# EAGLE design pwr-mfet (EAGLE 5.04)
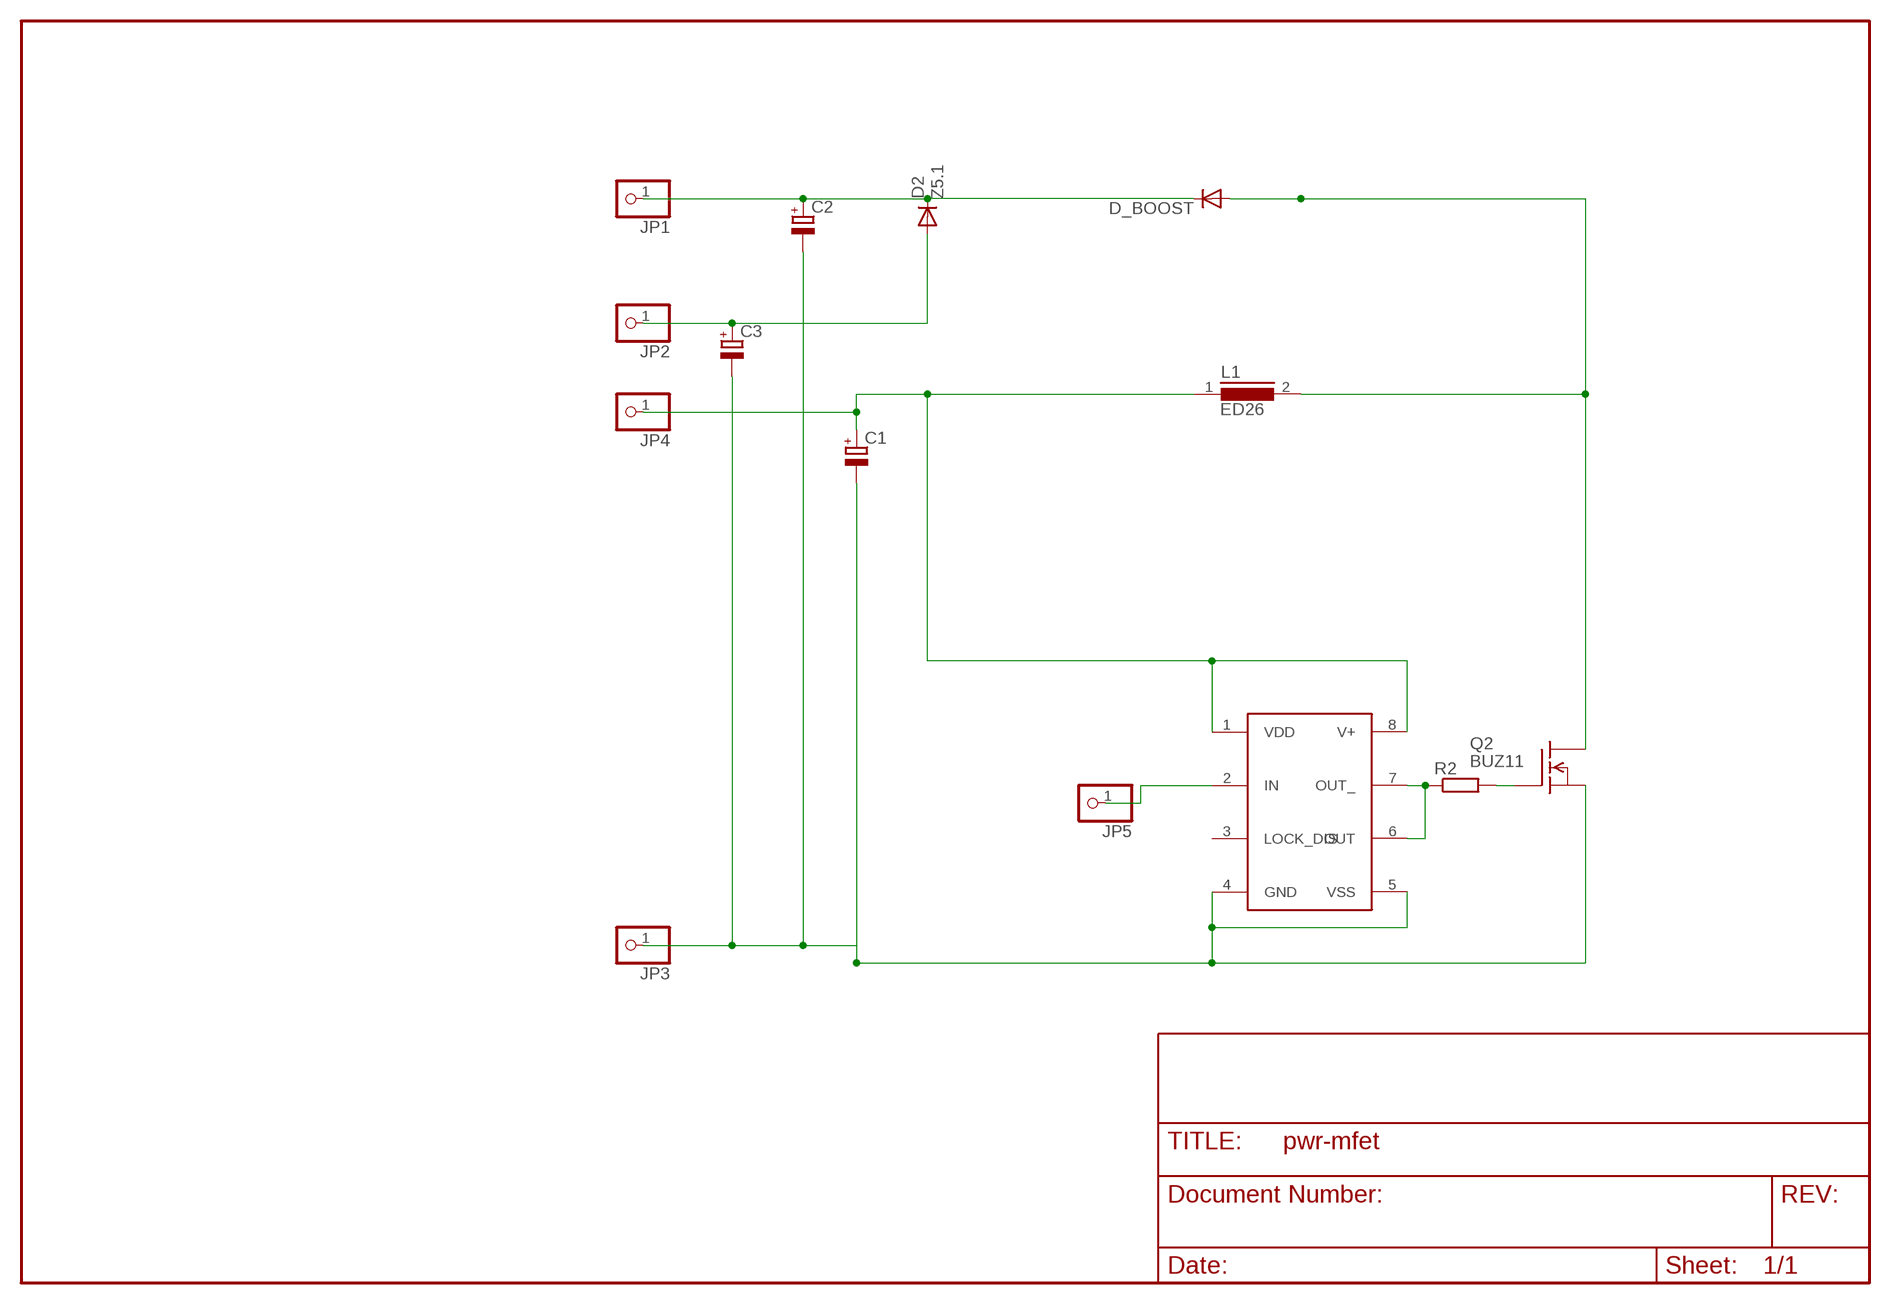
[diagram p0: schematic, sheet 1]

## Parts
C1  CPOL-EUE2.5-7  [E2,5-7]
C2  CPOL-EUE2.5-7  [E2,5-7]
C3  CPOL-EUE2-4  [E2-4]
D2  Z5.1  DIODE-D-2.5  [D-2.5]
D_BOOST  DIODE-D-10  [D-10]
IC1  TC4432X  [SO-08]
JP1  PINHD-1X1  [1X01]
JP2  PINHD-1X1  [1X01]
JP3  PINHD-1X1  [1X01]
JP4  PINHD-1X1  [1X01]
JP5  PINHD-1X1  [1X01]
L1  ED26  [ED26]
Q2  BUZ11  [TO220]
R2  R-EU_R1206  [R1206]

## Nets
GND: C1.- C2.- C3.- IC1.4(GND) IC1.5(VSS) JP3.1 Q2.3(S)
HOTSPOT: D_BOOST.A L1.2 Q2.2(D)
LOAD: C2.+ D2.C D_BOOST.C JP1.1
N$1: IC1.2(IN) JP5.1
N$2: C1.+ IC1.1(VDD) IC1.8(V+) JP4.1 L1.1
N$3: IC1.6(OUT) IC1.7(OUT_) R2.1
N$4: C3.+ D2.A JP2.1
N$6: Q2.1(G) R2.2
Unconnected: IC1.3(LOCK_DIS)

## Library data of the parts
C1-C3 = rcl(2):CPOL-EU: POLARIZED CAPACITOR, European symbol
D2 D_BOOST = diode:DIODE-: DIODE
IC1 = microchip:TC4432
JP1-JP5 = pinhead:PINHD-1X1: PIN HEADER
L1 = inductors:ED26: INDUCTOR
Q2 = transistor-fet:BUZ11: N-Channel Enhancement MOSFET 50V; 30A; 0,040Ohm
R2 = rcl-2:R-EU_: RESISTOR, European symbol

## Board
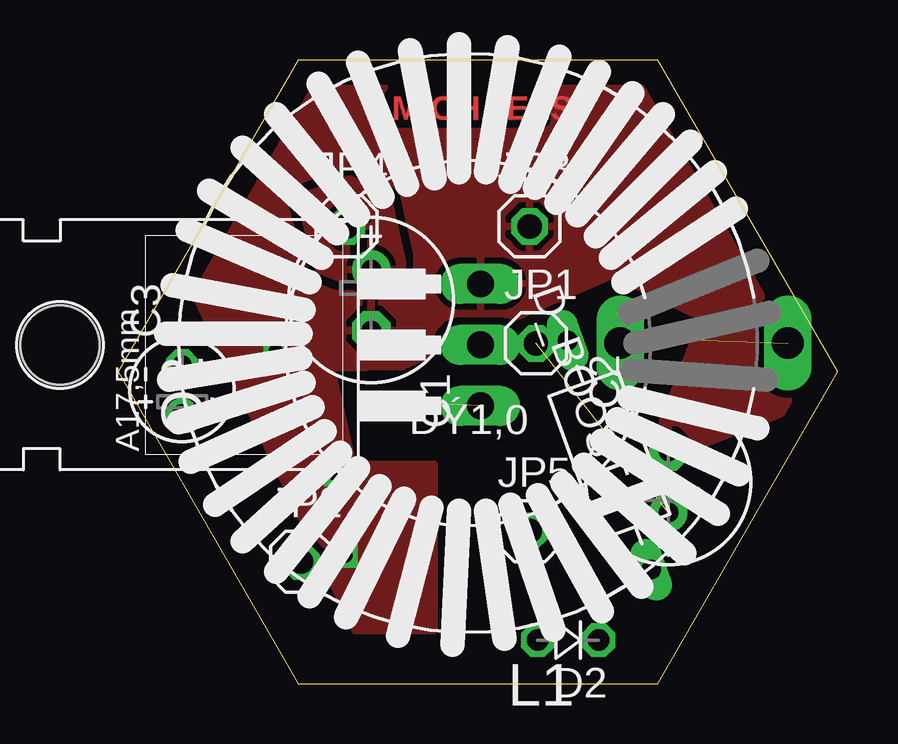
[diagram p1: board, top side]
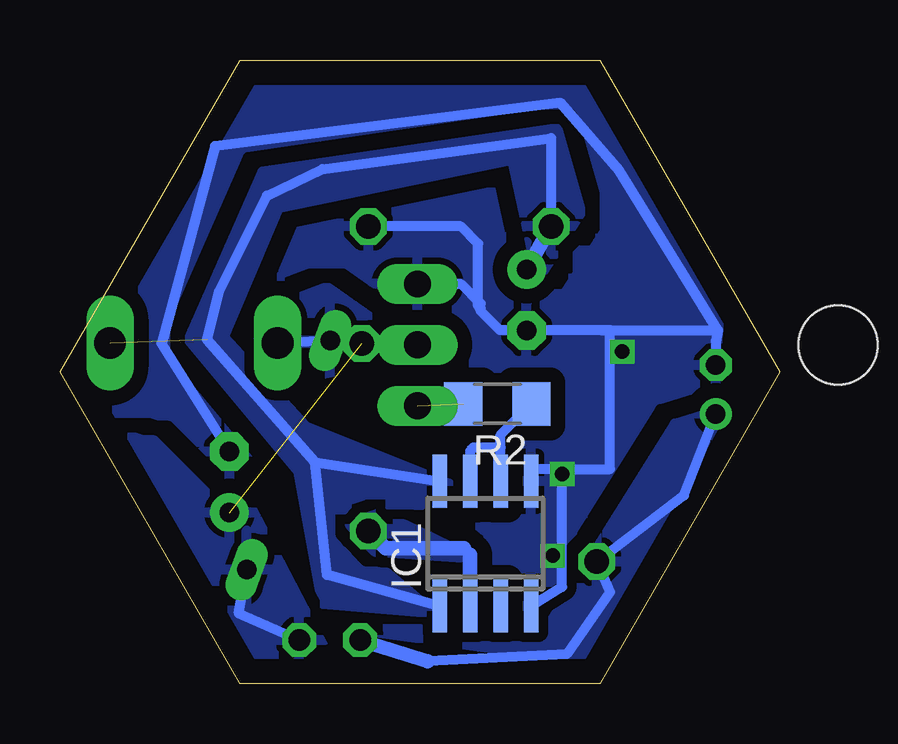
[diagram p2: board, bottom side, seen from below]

Size 30 x 25.98 mm. Coordinates in mm from the lower left corner, seen from the top.
Outline: 7.5,0 22.5,0 30,12.99 22.5,25.98 7.5,25.98 0,12.99 7.5,0
Copper layers (1*16): Top 0.035mm / dielectric 1.5mm / Bottom 0.035mm
Design rules "default": minimum track width 10mil, minimum drill 24mil, track to track 8mil, track to pad 8mil, pad to pad 8mil, via to via 8mil, smd to smd 8mil, copper to edge 40mil, drill to drill 8mil, minimum pad ring 10mil, minimum via ring 8mil, stop-mask expansion 4mil, vias tented up to drill 0mil, thermal gap 10mil

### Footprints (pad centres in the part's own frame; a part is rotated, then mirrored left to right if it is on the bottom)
E2,5-7 = drill 0.813 pad 1.6 round: + -1.27,0 | drill 0.813 pad 1.6 octagon: - 1.27,0
E2-4 = drill 0.813 pad 1.27 round: + -1.016,0 | drill 0.813 pad 1.27 octagon: - 1.016,0
D-2.5 = drill 0.9 octagon: A 1.27,0; C -1.27,0
D-10 = drill 0.813 long: A 5.08,0; C -5.08,0
SO-08 = smd 0.6 x 2.2: 1 -1.905,-2.6; 2 -0.635,-2.6; 3 0.635,-2.6; 4 1.905,-2.6; 5 1.905,2.6; 6 0.635,2.6; 7 -0.635,2.6; 8 -1.905,2.6
1X01 = drill 1.016 octagon: 1 0,0
ED26 = drill 1.321 long: 1 -13.335,0; 2 -6.35,0
TO220 = drill 1.118 long: 1 -2.54,-6.35; 2 0,-6.35; 3 2.54,-6.35 | hole 3.302: 0,11.176
R1206 = smd 1.6 x 1.803: 1 -1.422,0; 2 1.422,0

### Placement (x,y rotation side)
C1  10.54,15.97 270 top
C2  22.93,8.39 90 top
C3  2.66,12.25 90 top
D2  18.75,1.81 180 top
D_BOOST  20.48,9.52 110 top
IC1  12.27,5.83 0 bottom
JP1  17.41,14.17 0 top
JP2  7.62,5.08 0 top
JP3  17.14,19.05 0 top
JP4  9.53,19.05 0 top
JP5  17.14,6.35 0 top
L1  14.58,14.19 180 top
Q2  8.74,14.11 90 top
R2  11.76,11.65 180 bottom

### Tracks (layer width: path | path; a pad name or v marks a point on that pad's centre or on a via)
GND  (via drill 0.6)
  Bottom 0.406: IC1.4 9.06,4.03 v9.06,8.73 9.06,8.93 | 9.06,8.93 10.26,8.93 IC1.5 | 9.06,8.93 7.07,8.93 7.07,14.73 7.46,14.73 | 7.46,14.73 10.54,14.73 | 10.54,14.73 C1.- | C2.- 25.77,14.16 23.54,22.39 9.13,24.2 6.67,21.36 2.56,14.73 | 7.46,14.73 2.56,14.73 | C3.- 2.67,14.27 2.56,14.73 | 10.54,14.73 11.66,14.73 12.46,15.53 12.46,15.63 | 12.46,15.63 12.46,15.83 13.27,16.63 15.07,16.63 Q2.3 | JP3.1 13.29,19.05 12.56,18.33 12.56,15.73 12.46,15.63
  other vias: 9.46,5.33 6.57,13.83
  pour Bottom (isolate 0.61, rank 3): 0.1,14.8 7.17,26.7 21.9,26.43 30.2,15.1 22.07,2.43 7.17,2.33
  pour Top (isolate 0.305, rank 3): 22.34,26.09 28.2,17.6 28.5,11.6 21.96,9.03 24.36,15.23 20.66,17.03 11.87,13.23 8.87,13.13 9.77,9.13 13.16,9.13 13.16,2.23 9.87,2.23 2.1,18.5 7.37,26.2
HOTSPOT
  Bottom 0.406: Q2.2 D_BOOST.A L1.2
  pour Bottom: 15.56,14.23 18.86,16.53 22.07,15.33 21.07,12.53 17.36,13.23
LOAD  (1 unrouted)
  Bottom 0.406: D2.C 22.55,2.91 D_BOOST.C
  pour Bottom: 18.57,0.73 22.07,7.43 23.36,7.43 26.07,10.13 26.57,10.13 28,10.6 21.46,0.13
N$1
  Bottom 0.406: 12.9,5.37 13.16,5.63
  Bottom 0.61: IC1.2 12.9,5.37 | 13.16,5.63 16.43,5.63 JP5.1
  pour Bottom (isolate 0.61): 15.66,6.53 16.73,7 17.83,6.63 16.83,5.57 13.16,5.33
N$2  (1 unrouted)
  Bottom 0.406: 19.36,9.23 IC1.8 | 19.36,9.23 18.86,4.53 IC1.1 | 19.36,9.23 23.86,14.33 23.36,16.33 21.36,20.33 19.07,21.43 9.53,22.73 JP4.1
  Bottom 0.61: JP4.1 C1.+
  pour Bottom (isolate 0.406, rank 2): 10.06,16.83 8.27,19.63 9.27,23.13 21.57,21.33 24.66,14.33 20.07,8.83 19.07,3.33 14.37,2.93 17.46,5.53 13.77,8.33 19.77,10.73 23.16,14.43 20.86,19.83 11.16,21.83
  pour Top (isolate 0.305, rank 2): 9.66,21.03 11.27,20.13 11.87,17.43 10.46,16.43 8.37,17.23 7.57,20.23
N$3
  Bottom 0.406: IC1.6 11.63,9.83 | 11.63,9.83 11.63,10.36 R2.1 | IC1.7 12.9,9.7 12.77,9.83 11.63,9.83
N$4
  Bottom 0.406: C3.+ 3.98,7.83 JP2.1 7.07,3.81 8.87,1.23 14.68,0.93
  Bottom 0.61: 14.68,0.93 D2.A
  pour Bottom (isolate 0.406, rank 2): 1.47,11.73 1.9,11.1 6.67,0.73 18.36,2.33 9.77,2.23 4.37,10.83
N$6  (1 unrouted)

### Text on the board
Top: MICHAELS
